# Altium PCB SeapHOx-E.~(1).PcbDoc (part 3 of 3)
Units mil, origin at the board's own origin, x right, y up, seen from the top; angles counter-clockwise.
Board outline 7300 x 3625 mil, 4 copper layers (Top Layer, Internal Plane 1, Signal Layer 1, Bottom Layer), stack 30.634 mil thick; 244 components, 217 nets, 966 pads, 416 vias.
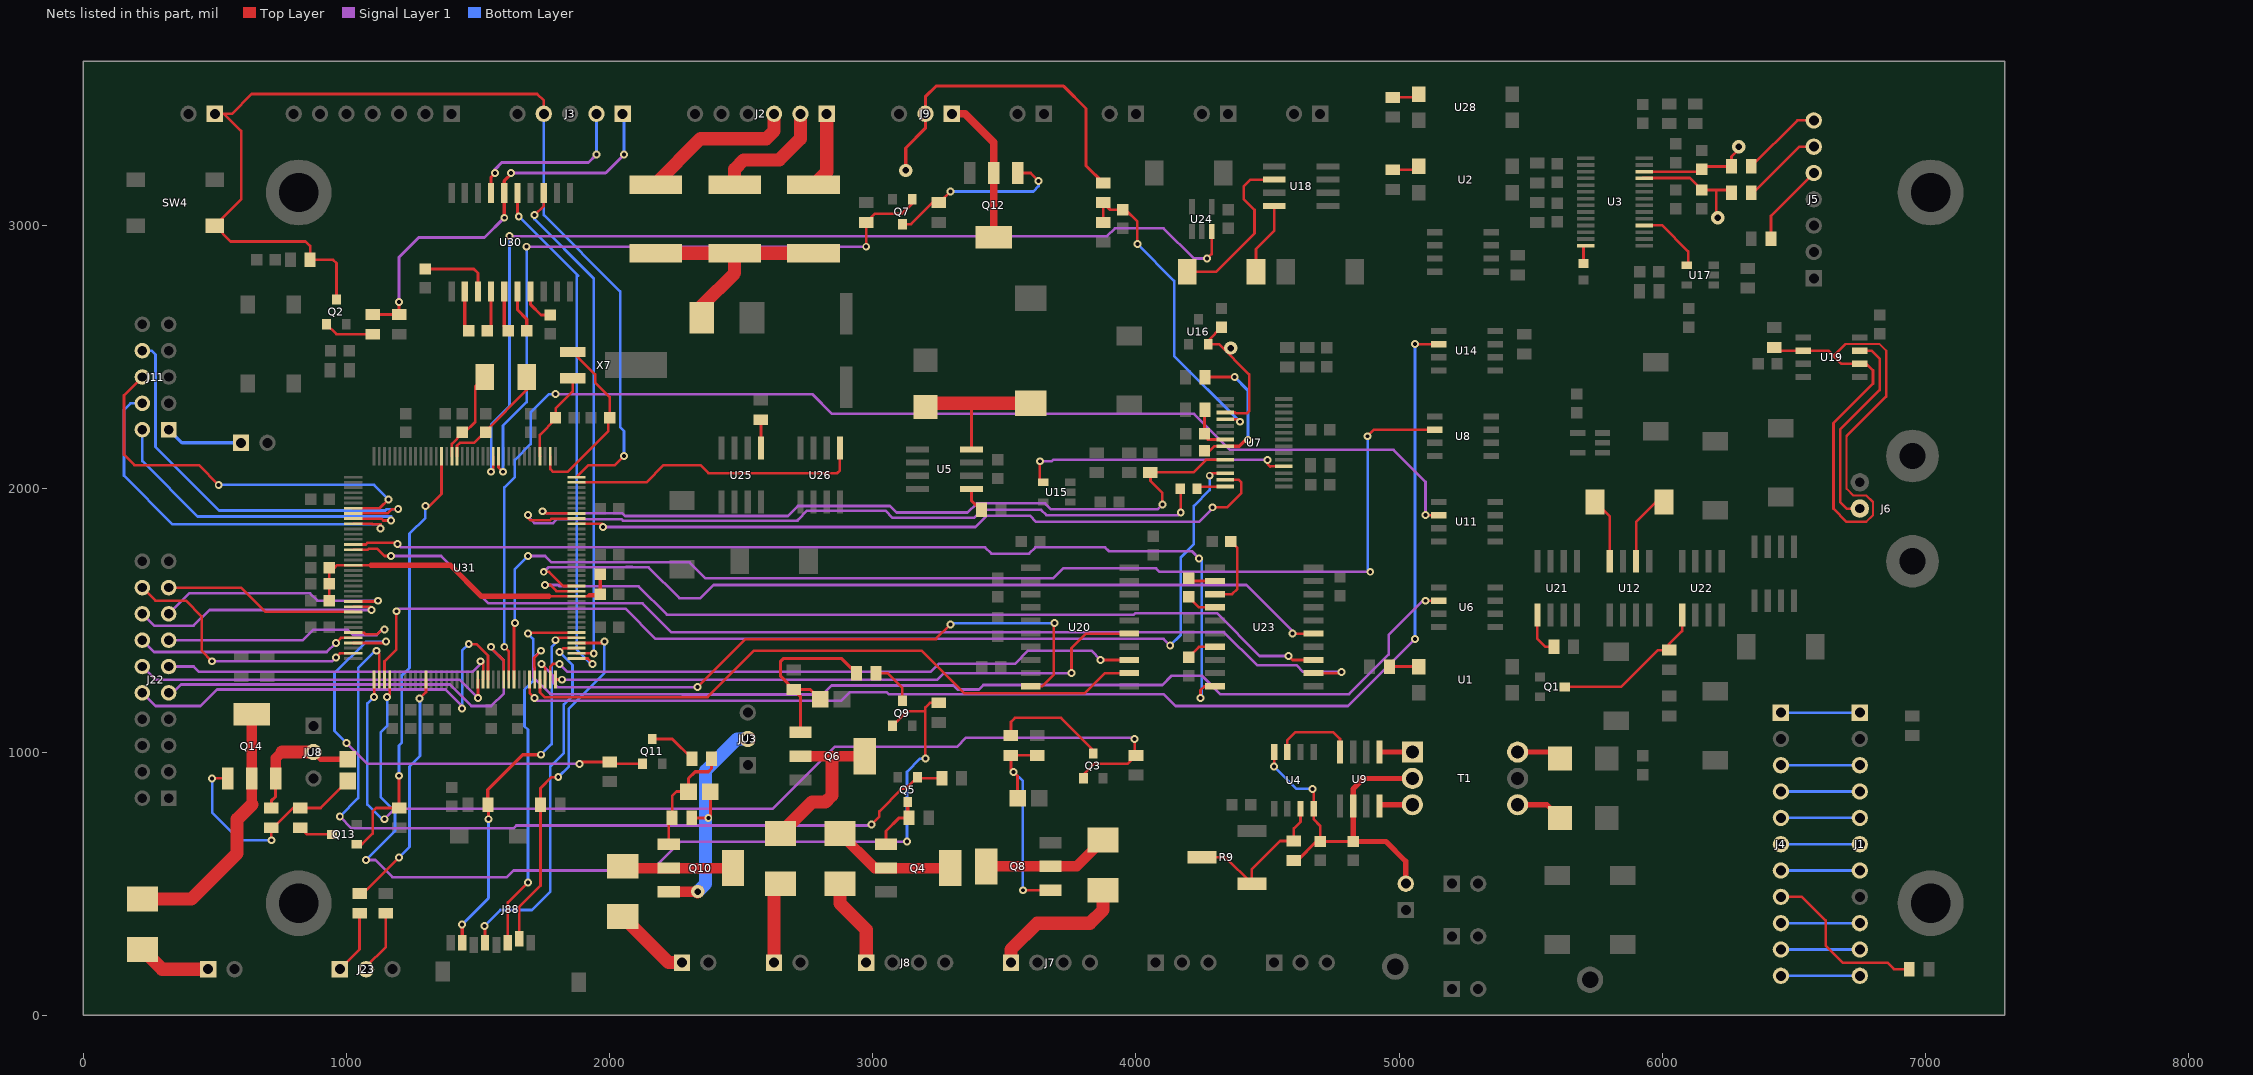
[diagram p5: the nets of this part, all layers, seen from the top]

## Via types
v1: diameter 30, hole 15, Top Layer to Bottom Layer, 378 vias
v2: diameter 50, hole 25, Top Layer to Bottom Layer, 38 vias

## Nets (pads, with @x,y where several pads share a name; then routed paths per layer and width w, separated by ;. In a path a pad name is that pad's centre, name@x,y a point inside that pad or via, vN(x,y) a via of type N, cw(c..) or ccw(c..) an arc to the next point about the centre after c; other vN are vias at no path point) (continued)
NetC41_1: C41.1 U12.2 | length 287
  Top Layer w10: U12.2@5900,1725 5900,1875 5975,1950 C41.1@6005.91,1950
NetC41_2: C41.2 U12.4 | length 248.2
  Top Layer w10: C41.2@5744.09,1950 5800,1894.09 U12.4@5800,1725
NetC42_1: C42.1 U23.2 | length 104.3
  Top Layer w10: C42.1@4200,1660.43 4210.43,1650 U23.2@4300,1650
NetC42_2: C42.2 U23.4 | length 116.4
  Top Layer w10: C42.2@4200,1589.57 4239.57,1550 U23.4@4300,1550
NetC43_1: C43.1 U23.7 | length 116.4
  Top Layer w10: C43.1@4200,1360.43 4239.57,1400 U23.7@4300,1400
NetC52_1: C52.1 U23.3 | length 283.5
  Top Layer w10: U23.3@4300,1600 4365,1600 4385,1620 4385,1775.43 C52.1@4360.43,1800
NetC53_2: C53.2 R33.1 U7.21 | length 184.4
  Top Layer w10: R33.1@4262.4,2300 4260.43,2298.03 C53.2@4260.43,2210 4260.43,2200 4272.64,2187.79 U7.21@4339,2187.79
NetC54_1: C54.1 C55.1 C56.1 C120.1 C121.1 U31.49 U31.126 | length 2218
  Top Layer w10: C54.1@935.43,1575 935.43,1625 C55.1@935.43,1640 ; C55.1@935.43,1658.43 C55.1@935.43,1640 ; 987,1710 1395,1710 1395.16,1709.84 1513.27,1591.73 1770,1591.73 U31.49@1874.24,1591.73 ; 1094.84,1709.84 U31.126@1025.76,1709.84 964.84,1709.84 955,1700 C120.1@935.43,1700 C55.1@935.43,1640 ; C121.1@1956.3,1591.73 U31.49@1874.24,1591.73 ; C121.1@1964.57,1600 1923.27,1600 1915,1591.73 U31.49@1874.24,1591.73
  Top Layer w12: C121.1@1964.57,1600 C56.1@1964.57,1675
  Top Layer w20: 1094.84,1709.84 1395.16,1709.84 1513.27,1591.73 1770,1591.73
NetC60_2: C60.2 R34.1 U7.22 | length 554.4
  Top Layer w10: C60.2@4260.43,2145 4280.43,2145 4297.64,2162.2 U7.22@4339,2162.2
  Top Layer w12: R34.1@4262.4,2425 v1(4375,2425) ; U7.22@4339,2162.2 4392.2,2162.2 4415,2185 v1(4425,2185)
  Bottom Layer w12: v1(4375,2425) 4425,2375 v1(4425,2185)
NetC62_1: C62.1 U18.2 | length 637.9
  Top Layer w10: C62.1@4194.09,2825 4305,2825 4450,2970 4450,3060 4410,3100 4410,3150 4435,3175 U18.2@4525,3175
NetC62_2: C62.2 U18.4 | length 278.6
  Top Layer w10: C62.2@4455.91,2825 4455.91,2910.91 4525,2980 U18.4@4525,3075
NetC101_1: C101.1 U30.7 | length 141.4
  Top Layer w12: U30.7@1700,2750 1700,2700 1739.57,2660.43 C101.1@1775,2660.43
NetC103_1: C103.1 U30.2 | length 156
  Top Layer w12: U30.2@1450,2750 1450,2614.57 C103.1@1464.57,2600
NetC103_2: C103.2 U30.4 | length 156
  Top Layer w12: C103.2@1535.43,2600 1550,2614.57 U30.4@1550,2750
NetC104_1: C104.1 U30.5 | length 156
  Top Layer w12: U30.5@1600,2750 1600,2614.57 C104.1@1614.57,2600
NetC104_2: C104.2 U30.6 | length 164.7
  Top Layer w12: U30.6@1650,2750 1650,2680 1685.43,2644.57 C104.2@1685.43,2600
NetC105_1: C105.1 U30.3 | length 276.4
  Top Layer w12: C105.1@1300,2835.43 1484.57,2835.43 1500,2820 U30.3@1500,2750
NetC122_1: C122.1 U31.74 X7.3 | length 698.1
  Top Layer w10: U31.74@1774.8,2124.24 1774.8,2075.2 1785,2065 1840,2065 1995,2220 1995,2264.57 C122.1@2000.43,2270 2000.43,2349.57 1945,2405 1945,2435 X7.3@1860,2520
NetC123_1: C123.1 U31.92 X6.2 | length 446.4
  Top Layer w10: U31.92@1420.47,2124.24 1420.47,2164.53 1430.94,2175 1485,2175 1522.5,2212.5 1522.5,2214.57 C123.1@1530,2214.57 1530,2220 1685,2375 X6.2@1685,2425
NetC124_1: C124.1 U31.93 X6.1 | length 357.8
  Top Layer w10: U31.93@1400.79,2124.24 1400.79,2170.79 1440,2210 C124.1@1440,2214.57 1449.57,2214.57 1490,2255 1490,2390 X6.1@1525,2425
NetC125_1: C125.1 U31.76 X7.1 | length 347.7
  Top Layer w10: U31.76@1735.43,2124.24 1735,2124.68 1735,2205 1795,2265 1795,2305 1860,2370 X7.1@1860,2420
NetD1_1: D1.1 T1.6 | length 171.8
  Top Layer w10: D1.1@5586.42,1000 D1.1@5611.42,975
  Top Layer w20: T1.6@5450,1000 D1.1@5586.42,1000
NetD2_1: D2.1 J2.1 | length 290.7
  Top Layer w50: D2.1@2775,3155 2825,3205 J2.1@2825,3425
NetD2_2: D2.2 D3.2 D7.2 FS1.1 | length 896.8
  Top Layer w50: D7.2@2175,2895 D3.2@2475,2895 ; FS1.1@2350,2650 2350,2695 2475,2820 D3.2@2475,2895 ; D2.2@2775,2895 D3.2@2475,2895
NetD3_1: D3.1 J2.2 | length 452.6
  Top Layer w50: D3.1@2475,3155 2475,3215 2510,3250 2645,3250 2725,3330 J2.2@2725,3425
NetD4_1: D4.1 T1.4 | length 182.1
  Top Layer w20: T1.4@5450,800 5561.42,800 D4.1@5611.42,750
NetD7_1: D7.1 J2.3 | length 602.8
  Top Layer w50: D7.1@2175,3155 2175,3160 2345,3330 2595,3330 2625,3360 J2.3@2625,3425
NetD8_2: D8.2 L1.1 U5.4 | length 602.7
  Top Layer w10: D8.2@3200,2311.42 3206.42,2305 3206.42,2325 D8.2@3213.58,2325 ; U5.4@3375,2150 3375,2325 3375,2330
  Top Layer w50: D8.2@3213.58,2325 3375,2325 L1.1@3600,2325
NetD9_1: D9.1 Q6.1 R29.1 R37.2 | length 731.2
  Top Layer w12: Q6.1@2725,1075 2725,1212.6 R29.1@2700,1237.6 ; D9.1@2800,1200 2762.4,1237.6 R29.1@2700,1237.6 ; R37.2@2937.6,1300 2882.6,1355 2660,1355 2650,1345 2650,1287.6 R29.1@2700,1237.6
NetD10_1: D10.1 Q8.1 R19.1 R38.2 | length 842.5
  Top Layer w10: D10.1@3550,825 3550,910 v1(3535,925) 3525,935 R38.2@3525,987.6 R19.1@3625,987.6 ; v1(3570,475) Q8.1@3675,475
  Bottom Layer w10: v1(3535,925) 3570,890 v1(3570,475)
NetD11_1: D11.1 Q10.1 R31.1 R39.2 | length 447.9
  Top Layer w10: Q10.1@2225,650 2225,737.4 R31.1@2237.6,750 2237.6,832.6 2255,850 D11.1@2300,850
  Top Layer w12: D11.1@2300,850 2300,900 2325,925 2375,925 2387.4,937.4 R39.2@2387.4,975
NetD11_2: D11.2 JU3.2 Q10.3 R31.2 | length 958.5
  Top Layer w12: R31.2@2312.4,750 v1(2375,750) 2383,758 D11.2@2383,850
  Top Layer w40: Q10.3@2225,468.9 v2@2333.9,468.9
  Top Layer w50: v2@2333.9,468.9 v2(2335,470)
  Bottom Layer w50: v2(2335,470) 2365,500 2365,750 2365,930 2485,1050 JU3.2@2525,1050
NetD12_1: D12.1 Q14.1 R42.1 R50.2 | length 869.6
  Top Layer w10: v1(490,900) Q14.1@550,900 ; v1(715,665) R42.1@715,712.6 722.6,712.6 797.4,787.4 R50.2@825,787.4 902.4,787.4 D12.1@1005,890
  Bottom Layer w10: v1(490,900) 490,770 595,665 v1(715,665)
NetD12_2: D12.2 JU8.2 Q14.3 R42.2 | length 490.4
  Top Layer w12: R42.2@715,787.4 715,815 731.1,831.1 Q14.3@731.1,900
  Top Layer w20: JU8.2@875,1000 902,973 D12.2@1005,973
  Top Layer w40: Q14.3@731.1,900 731.1,976.1 755,1000
  Top Layer w50: 755,1000 JU8.2@875,1000
NetFS2_1: FS2.1 J8.1 | length 341.4
  Top Layer w50: FS2.1@2875,500 2875,425 2975,325 J8.1@2975,200
NetFS2_2: FS2.2 Q4.2 Q4.4 | length 473.7
  Top Layer w40: FS2.2@2875,691.34 3006.89,559.45 Q4.2@3050,559.45 Q4.4@3294.1,559.45
NetFS3_1: FS3.1 J7.1 | length 537.1
  Top Layer w50: J7.1@3525,200 3525,250 3625,350 3825,350 3875,400 FS3.1@3875,475
NetFS3_2: FS3.2 Q8.2 Q8.4 | length 485.8
  Top Layer w40: Q8.4@3430.91,565.55 Q8.2@3675,565.55 3774.21,565.55 FS3.2@3875,666.34
NetFS4_1: FS4.1 J10.1 | length 310.4
  Top Layer w50: J10.1@2625,200 2625,475 FS4.1@2650,500
NetFS4_2: FS4.2 Q6.2 Q6.4 | length 762.5
  Top Layer w10: Q6.2@2725,984.45 2795,984.45 2804.45,975 2845,975
  Top Layer w40: Q6.2@2725,984.45 Q6.4@2969.09,984.45
  Top Layer w50: FS4.2@2650,691.34 2768.66,810 2820,810 2845,835 2845,975
NetFS5_1: FS5.1 J12.1 | length 297.5
  Top Layer w50: FS5.1@2050,375 2225,200 J12.1@2275,200
NetFS5_2: FS5.2 Q10.2 Q10.4 | length 435.7
  Top Layer w10: FS5.2@2050,566.34 2056.89,566.34 FS5.2@2056.89,559.45
  Top Layer w40: FS5.2@2056.89,559.45 Q10.2@2225,559.45 Q10.4@2469.09,559.45
  Top Layer w50: Q10.4@2462.2,566.34 Q10.4@2469.09,559.45
NetFS6_1: FS6.1 J20.1 | length 281.1
  Top Layer w50: FS6.1@225,250 300,175 J20.1@475,175
NetFS6_2: FS6.2 Q14.2 Q14.4 | length 984
  Top Layer w40: 640.55,800.55 Q14.2@640.55,900 Q14.4@640.55,1144.09
  Top Layer w50: FS6.2@225,441.34 411.34,441.34 585,615 585,745 640.55,800.55
NetJ1_1: J1.1 J4.1 | length 300
  Bottom Layer w10: J4.1@6450,1150 J1.1@6750,1150
NetJ1_3: J1.3 J4.3 | length 300
  Bottom Layer w10: J4.3@6450,950 J1.3@6750,950
NetJ1_4: J1.4 J4.4 | length 300
  Bottom Layer w10: J4.4@6450,850 J1.4@6750,850
NetJ1_5: J1.5 J4.5 | length 300
  Bottom Layer w10: J4.5@6450,750 J1.5@6750,750
NetJ1_6: J1.6 J4.6 | length 300
  Bottom Layer w10: J4.6@6450,650 J1.6@6750,650
NetJ1_7: J1.7 J4.7 | length 300
  Bottom Layer w10: J4.7@6450,550 J1.7@6750,550
NetJ1_9: J1.9 J4.9 | length 300
  Bottom Layer w10: J4.9@6450,350 J1.9@6750,350
NetJ1_10: J1.10 J4.10 | length 300
  Bottom Layer w10: J4.10@6450,250 J1.10@6750,250
NetJ1_11: J1.11 J4.11 | length 300
  Bottom Layer w10: J4.11@6450,150 J1.11@6750,150
NetJ3_2: J3.2 U30.17 | length 660
  Top Layer w12: U30.17@1550,3124.02 1550,3185 v1(1565,3200)
  Signal Layer 1 w12: v1(1565,3200) 1565,3215 1590,3240 1920,3240 v1(1950,3270)
  Bottom Layer w12: v1(1950,3270) J3.2@1950,3425
NetJ4_8: J4.8 R15.1 | length 657.2
  Top Layer w10: J4.8@6450,450 6530,450 6620,360 6620,265 6685,200 6855,200 6880,175 R15.1@6937.6,175
NetJ5_5: J5.5 R43.2 | length 317.4
  Top Layer w10: R43.2@6412.4,2950 6412.4,3037.4 J5.5@6575,3200
NetJ5_6: J5.6 R23.2 | length 310.1
  Top Layer w10: R23.2@6337.4,3125 6345,3125 6520,3300 J5.6@6575,3300
NetJ5_7: J5.7 R24.2 | length 310.1
  Top Layer w10: R24.2@6337.4,3225 6512.4,3400 J5.7@6575,3400
NetJ6_1: J6.1 U19.3 | length 779.9
  Top Layer w10: J6.1@6750,1925 6700,1925 6675,1950 6675,2225 6825,2375 6825,2495 6795,2525 U19.3@6750,2525
NetJ9_1: J9.1 Q12.2 Q12.4 | length 564.4
  Top Layer w30: J9.1@3300,3425 3350,3425 3459.45,3315.55 Q12.2@3459.45,3200 Q12.4@3459.45,2955.91
NetJ9_2: J9.2 R36.1 | length 1282.4
  Top Layer w12: v2(3125,3210) 3125,3295 3200,3370 J9.2@3200,3425 3200,3490 3240,3530 3725,3530 3810,3445 3810,3227.4 R36.1@3875,3162.4
NetJ11_1: J11.1 JU7.1 | length 295.7
  Bottom Layer w12: J11.1@325,2225 375,2175 JU7.1@600,2175
NetJ23_1: J23.1 R60.1 | length 243.7
  Top Layer w10: J23.1@975,175 1050,250 R60.1@1050,387.6
NetJ23_2: J23.2 R61.1 | length 243.7
  Top Layer w10: J23.2@1075,175 1075,185 1150,260 R61.1@1150,387.6
NetQ1_3: Q1.3 R5.2 U22.5 | length 607
  Top Layer w10: Q1.3@5629.49,1247.6 5842.6,1247.6 5982.4,1387.4 R5.2@6025,1387.4 6025,1410 6075,1460 U22.5@6075,1520.28
NetQ2_1: Q2.1 R55.1 | length 190.5
  Top Layer w10: Q2.1@925,2625 962.4,2587.6 R55.1@1100,2587.6
NetQ3_3: Q3.3 R38.1 | length 435
  Top Layer w10: R38.1@3525,1062.4 3525,1115 3540,1130 3715,1130 3837.4,1007.6 Q3.3@3837.4,994.49
NetQ4_1: Q4.1 Q5.3 R22.1 | length 206.2
  Top Layer w12: Q4.1@3050,650 3050,700 3100,750 R22.1@3132.6,750 ; R22.1@3132.6,757.6 Q5.3@3132.6,810.51
NetQ7_3: Q7.3 Q12.1 R26.1 | length 689.7
  Top Layer w10: Q7.3@3112.6,3005.51 3145.51,3005.51 3227.4,3087.4 R26.1@3250,3087.4 3252.4,3087.4 v1(3295,3130) ; Q12.1@3550,3200 3600,3200 v1(3630,3170)
  Bottom Layer w10: v1(3295,3130) 3610,3130 3630,3150 v1(3630,3170)
NetQ9_3: Q9.3 R37.1 | length 171.9
  Top Layer w10: R37.1@3012.4,1300 3055,1300 3112.4,1242.6 Q9.3@3112.4,1194.49
NetQ11_3: Q11.3 R39.1 | length 181
  Top Layer w10: Q11.3@2162.4,1049.49 2238.11,1049.49 R39.1@2312.6,975
NetQ13_3: Q13.3 R50.1 | length 130.9
  Top Layer w10: R50.1@825,712.6 850.2,687.4 Q13.3@945.51,687.4
NetR1_2: R1.2 U1.1 | length 112.6
  Top Layer w10: R1.2@4962.4,1325 U1.1@5075,1325
NetR7_1: R7.1 R9.1 R9.2 U4.7 | length 623.9
  Top Layer w10: R9.2@4250,600 4340,600 R9.1@4440,500 4440,555 4547.4,662.4 R7.1@4600,662.4 4600,710 4625,735 U4.7@4625,785
NetR8_2: R8.2 U5.1 | length 97.1
  Top Layer w12: U5.1@3375,2000 3375,1955 3410,1920 R8.2@3412.6,1920
NetR10_1: R10.1 U21.5 | length 165.3
  Top Layer w10: U21.5@5525,1520.28 5525,1430 5555,1400 R10.1@5587.6,1400
NetR11_1: R11.1 U25.5 | length 107.9
  Top Layer w12: U25.5@2575,2154.72 R11.1@2575,2262.6
NetR17_2: R17.2 U3.28 | length 71.2
  Top Layer w10: R17.2@5700,2856.5 5700,2918.5 U3.28@5706.5,2925
NetR21_1: R21.1 U19.2 U19.6 | length 2173.7
  Top Layer w8: 6695,2550 6825,2550 6850,2525 ; 6700,1875 6775,1875 6800,1900 6800,1950 6775,1975 6725,1975 6700,2000 6700,2200
  Top Layer w10: R21.1@6425,2537.6 6437,2537.6 6437,2525 U19.6@6535,2525 6630,2525 6650,2505 ; 6695,2550 6650,2505 ; 6700,1875 6650,1925 6650,2250 6800,2400 6800,2450 6775,2475 U19.2@6750,2475 6680,2475 6650,2505 ; 6700,2200 6850,2350 6850,2525
NetR53_2: R53.2 U7.28 | length 116.2
  Top Layer w10: R53.2@4231.5,2000 4231.5,2008.66 4240.16,2008.66 U7.28@4339,2008.66
NetR56_2: R56.2 U2.1 | length 92
  Top Layer w10: R56.2@4975,3212.4 5062.4,3212.4 U2.1@5067,3212.4
NetR59_2: R59.2 U28.1 | length 92
  Top Layer w10: R59.2@4975,3487.4 5062.4,3487.4 U28.1@5067,3487.4
NetT1_1: T1.1 U9.1 | length 125
  Top Layer w20: U9.1@4925,1000 T1.1@5050,1000
NetT1_3: T1.3 U9.8 | length 129.7
  Top Layer w10: U9.8@4925,795.28 4925,800 U9.8@4929.72,800
  Top Layer w20: U9.8@4929.72,800 T1.3@5050,800
NetU3_4: U3.4 U17.4 | length 266.4
  Top Layer w10: U3.4@5925,3001.77 5998.23,3001.77 6097.64,2902.36 U17.4@6097.64,2849.8
NetU4_3: U4.3 U9.4 | length 317.8
  Top Layer w10: U4.3@4575,1000 4575,1045 4605,1075 4750,1075 4775,1050 U9.4@4775,1000
NetU7_4: U7.4 U15.4 | length 1033.1
  Top Layer w10: v1(3635,2105) 3635,2037.44 U15.4@3647.64,2024.8 ; v1(4500,2110) 4500,2095 4510,2085 4510,2085.43 U7.4@4561,2085.43
  Signal Layer 1 w10: v1(3635,2105) 3680,2105 3685,2110 v1(4500,2110)
PB5: J22.17 U31.135 | length 739
  Top Layer w10: J22.17@325,1625 600,1625 692.32,1532.68 U31.135@1025.76,1532.68
PD6: J22.18 U31.143 | length 1005.4
  Top Layer w10: J22.18@225,1625 275,1575 390,1575 450,1515 450,1385 v1(490,1345) ; v1(960,1360) 975.2,1375.2 U31.143@1025.76,1375.2
  Signal Layer 1 w10: v1(490,1345) 945,1345 v1(960,1360)
PE4: J22.13 U31.139 | length 982.7
  Top Layer w10: U31.139@1025.76,1453.94 1066.47,1453.94 1073.4,1447 1117,1447 1135,1465 v1(1145,1465)
  Signal Layer 1 w10: J22.13@325,1425 835,1425 875,1465 1005,1465 1025,1445 1115,1445 1135,1465 v1(1145,1465)
PE5: J22.14 U31.140 | length 841.9
  Top Layer w10: v1(960,1415) 979.25,1434.25 U31.140@1025.76,1434.25
  Signal Layer 1 w10: J22.14@225,1425 270,1380 925,1380 v1(960,1415)
PE6: J22.15 U31.133 | length 935.2
  Top Layer w10: U31.133@1025.76,1572.05 v1@1115,1572.05 ; v1@1115,1570 v1(1120,1575)
  Signal Layer 1 w10: J22.15@325,1525 403,1603 862,1603 890,1575 v1(1120,1575)
PE7: J22.16 U31.134 | length 997.9
  Top Layer w10: U31.134@1025.76,1552.36 1092.64,1552.36 1095,1550 v1(1095,1540)
  Signal Layer 1 w10: J22.16@225,1525 270,1480 420,1480 480,1540 1085,1540 1090,1545 v1@1095,1550
"PH +5V": C25.1 C36.2 JU2.2 R7.2 T1.2 U4.4 U4.8 U9.6 | length 1459.8
  Top Layer w10: v1(4525,945) U4.4@4525,1000 ; R7.2@4600,587.6 R7.2@4612.6,587.6 ; v1(4670,860) 4675,855 U4.8@4675,785 4675,745 4700,720 C36.2@4700,660.43 C36.2@4685.43,660.43
  Top Layer w12: R7.2@4612.6,587.6 C36.2@4685.43,660.43 ; C36.2@4700,660.43 C25.1@4825,660.43
  Top Layer w20: JU2.2@5025,500 5025,585 4949.57,660.43 C25.1@4825,660.43 U9.6@4825,795.28 4825,860 4865,900 T1.2@5050,900
  Bottom Layer w10: v1(4525,945) 4610,860 v1(4670,860)
PRES_V_DIV: C15.2 R35.1 R36.2 U7.18 | length 1219.7
  Top Layer w10: R35.1@3875,3012.4 R36.2@3875,3087.6 3902.16,3060.43 C15.2@3950,3060.43 3959.57,3060.43 4005,3015 v1(4005,2930) ; U7.18@4339,2264.57 4390.43,2264.57 4395,2260 v1(4395,2255)
  Bottom Layer w10: v1(4005,2930) 4145,2790 4145,2505 v1(4395,2255)
RED-LED: R60.2 U31.11 | length 929.8
  Top Layer w10: R60.2@1050,462.4 1062.4,462.4 v1(1200,600) ; v1(1277.5,1203.77) 1277.5,1202.5 1278.13,1203.13 1302.36,1227.36 U31.11@1302.36,1275.76
  Bottom Layer w10: v1(1200,600) 1240,640 1240,945 1280,985 1280,1201.27 v1(1277.5,1203.77)
RSRXD: J3.1 R54.2 R55.2 U30.16 | length 1588.2
  Top Layer w12: R55.2@1100,2662.4 R54.2@1200,2662.4 v1(1200,2710) ; v1(1600,3030) U30.16@1600,3124.02 1600,3170 v1@1630,3200
  Signal Layer 1 w12: v1(1200,2710) 1200,2880 1275,2955 1525,2955 v1(1600,3030) ; v1(1625,3200) 1985,3200 v1(2055,3270)
  Bottom Layer w12: J3.1@2050,3425 2055,3430 v1(2055,3270)
SSI0CLK: J88.5 U31.39 | length 1405.1
  Top Layer w10: v1(1810,1380) 1824.88,1394.88 U31.39@1874.24,1394.88
  Top Layer w12: v1(1525,340) 1526.77,338.23 J88.5@1526.77,275
  Bottom Layer w10: v1(1525,340) 1585,400 1705,400 1775,470 1775,945 1826,996 1826,1181 1859,1214 1859,1331 v1(1810,1380)
SSI0FSS: J88.2 R45.1 U31.40 | length 1385.8
  Top Layer w10: J88.2@1656.69,290.75 1656.69,411.69 1737.6,492.6 R45.1@1737.6,800 1737.6,862.6 1780,905 v1(1805,905) ; U31.40@1874.24,1414.57 1974.57,1414.57 v1(1980,1420)
  Bottom Layer w10: v1(1805,905) 1845,945 1845,1165 1980,1300 v1(1980,1420)
SSI0RX: J88.7 R51.1 U31.41 | length 1423.3
  Top Layer w10: v1(1795,1425) 1804.25,1434.25 U31.41@1874.24,1434.25
  Top Layer w12: v1(1440,345) 1440.16,344.84 J88.7@1440.16,275 ; v1(1540,745) 1540,797.4 R51.1@1537.4,800 1537.4,857.4 1670,990 v1(1740,990)
  Bottom Layer w10: v1(1740,990) 1780,1030 1780,1400 1795,1415 v1(1795,1425)
  Bottom Layer w12: v1(1440,345) 1540,445 v1(1540,745)
SSI0TX: J88.3 U31.42 | length 1419.9
  Top Layer w10: J88.3@1613.39,275 1613.39,428.39 v1(1690,505) ; v1(1690,1450) 1693.94,1453.94 U31.42@1874.24,1453.94
  Bottom Layer w10: v1(1690,505) 1690,1085 1677,1098 1677,1237 1710,1270 1710,1430 v1(1690,1450)
SSI1CLK: R53.1 U31.64 | length 2875.5
  Top Layer w10: v1(1690,1900) 1700,1900 1690,1890 1699.69,1880.31 1773.29,1880.31 1779.99,1887.01 U31.64@1874.24,1887.01 ; R53.1@4168.5,2000 4170,1998.5 v1(4170,1910)
  Signal Layer 1 w10: v1(1690,1900) 1700,1900 1692.5,1892.5 1715,1870 1785,1870 1800,1885 2044.95,1885 2050.95,1879 2715,1879 2715,1882 2750,1917 3048,1917 3075,1890 3385,1890 3415,1920 3640,1920 3660,1900 4160,1900 v1(4170,1910)
SSI1FSS: R47.1 U7.24 U31.65 | length 3017.5
  Top Layer w10: v1(1745,1915) v1@1755,1915 ; v1@1753.31,1906.69 U31.65@1874.24,1906.69 ; R47.1@4070,2047.6 R47.1@4055,2062.6 ; v1(4100,1940) 4100,1985 4055,2030 R47.1@4055,2062.6 ; U7.24@4339,2111.02 4338.32,2110.35 4265.35,2110.35 4217.6,2062.6 R47.1@4055,2062.6
  Signal Layer 1 w10: v1(1745,1915) 1755,1915 1763,1907 2048.4,1907 2058.4,1897 2677,1897 2715,1935 3065,1935 3090,1910 3360,1910 3395,1945 3655,1945 3678,1922 4082,1922 v1(4100,1940)
SSI1RX: U7.26 U31.3 | length 4053.8
  Top Layer w10: U31.3@1144.88,1275.76 1144.88,1344.88 1190,1390 v1(1190,1535) ; v1(4280,2050) 4289.84,2059.84 U7.26@4339,2059.84
  Signal Layer 1 w10: v1(1190,1535) 1200,1545 2060,1545 2175,1430 4105,1430 v1(4130,1405)
  Bottom Layer w10: v1@4127.5,1402.5 v1(4130,1405) 4170,1445 4170,1740 4220,1790 4220,1935 4280,1995 v1(4280,2050)
SSI1TX: U7.27 U31.63 | length 2715.9
  Top Layer w10: U31.63@1874.24,1867.32 1972.68,1867.32 1975,1865 v1(1975,1855) ; v1(4290,1930) 4345,1930 4400,1985 4400,2025 4390.75,2034.25 U7.27@4339,2034.25
  Signal Layer 1 w10: v1(1975,1855) 3390,1855 3433,1898 3598,1898 3621,1875 4240,1875 v1@4292.5,1927.5
SSI2CLK: J22.9 U31.26 | length 1681.3
  Top Layer w10: v1(1550,1400) 1555,1395 1555,1390 1598,1347 1598,1276.12 U31.26@1597.64,1275.76
  Signal Layer 1 w10: J22.9@325,1225 340,1225 372,1257 1393,1257 1475,1175 1550,1175 1598,1223 1598,1347 1550,1395 v1(1550,1400)
SSI2FSS: J22.10 U31.23 | length 1735.6
  Top Layer w10: v1(1465,1410) 1495,1410 1538,1367 1538,1276.34 U31.23@1538.58,1275.76
  Signal Layer 1 w10: J22.10@225,1225 275,1175 446,1175 509,1238 1377,1238 1440,1175 v1(1440,1165)
  Bottom Layer w10: v1(1440,1165) 1440,1385 v1(1465,1410)
SSI2RX: J22.11 U31.22 | length 1295.4
  Top Layer w10: v1(1510,1345) 1520,1345 1520,1276.86 U31.22@1518.9,1275.76
  Signal Layer 1 w10: J22.11@325,1325 420,1325 440,1305 1480,1305 1510,1335 v1(1510,1345)
SSI2TX: J22.12 U31.21 | length 1395.8
  Top Layer w10: U31.21@1499.21,1275.76 1500,1274.97 v1(1500,1205)
  Signal Layer 1 w10: J22.12@225,1325 275,1275 1430,1275 v1(1500,1205)
SSI3CLK: U6.2 U31.32 | length 3962.3
  Top Layer w10: U31.32@1715.75,1275.76 1715.75,1320.65 1714,1322.4 1714,1359 v1(1740,1385) ; v1(5100,1575) U6.2@5150,1575
  Signal Layer 1 w10: v1(1740,1385) 1710,1355 1710,1285 1775,1220 2275,1220 2276,1219 2809,1219 2843,1253 3307,1253 3322,1238 3403,1238 3420,1255 4100,1255 4135,1290 4250,1290 4320,1220 4810,1220 4960,1370 4960,1445 5090,1575 v1(5100,1575)
SSI3FSS: U14.2 U31.31 | length 4779
  Top Layer w10: U31.31@1696.06,1275.76 1696.06,1223.94 v1(1715,1205) ; v1(5060,2550) U14.2@5150,2550
  Signal Layer 1 w10: v1(1715,1205) 1725,1195 2880,1195 2913,1228 3052,1228 3060,1220 4105,1220 4150,1175 4805,1175 v1(5060,1430)
  Bottom Layer w10: v1(5060,1430) v1(5060,2550)
SSI3RX: U8.6 U31.28 | length 4532
  Top Layer w10: U31.28@1637.01,1275.76 1637.01,1487.01 v1(1640,1490) ; v1(4880,2200) 4905,2225 U8.6@5135,2225
  Signal Layer 1 w10: v1(1690,1745) 1705,1745 1755,1745 1779,1721 2304,1721 2365,1660 3685,1660 3723,1698 4076.6,1698 4089.6,1685 v1(4890,1685)
  Bottom Layer w10: v1(1640,1490) 1640,1695 v1(1690,1745) ; v1(4880,2200) 4880,1695 v1(4890,1685)
SSI3TX: U11.2 U31.27 | length 4806.8
  Top Layer w10: v1(1600,1400) 1617.32,1382.68 U31.27@1617.32,1275.76 ; v1(5100,1900) U11.2@5150,1900
  Signal Layer 1 w10: v1(1795,2360) 2770,2360 2845,2285 4221,2285 4358,2148 4979,2148 5100,2027 v1(5100,1900)
  Bottom Layer w10: v1(1600,1400) 1600,2005 1640,2045 1640,2110 1700,2170 1700,2290 1770,2360 v1(1795,2360)
SWITCH_2.5V: U24.3 U31.85 | length 3806.9
  Top Layer w10: v1(1550,2065) 1558.27,2073.27 U31.85@1558.27,2124.24 ; v1(4270,2875) 4287.4,2892.4 U24.3@4287.4,2978
  Signal Layer 1 w10: v1(1620,2960) 3890,2960 3920,2990 4105,2990 4220,2875 v1(4270,2875)
  Bottom Layer w10: v1(1550,2065) 1550,2245 1620,2315 v1(1620,2960)
SWITCH_AUX_POWER1: Q11.1 R32.2 U31.141 | length 1808.6
  Top Layer w10: U31.141@1025.76,1414.57 1144.57,1414.57 v1(1150,1420) ; v1(1885,955) 1892.4,962.4 R32.2@2000,962.4 ; R32.2@2007.4,955 Q11.1@2125,955
  Signal Layer 1 w10: v1(1000,1035) 1080,955 v1(1885,955)
  Bottom Layer w10: v1(1000,1035) 955,1080 955,1300 1074,1419 1149,1419 v1(1150,1420)
SWITCH_AUX_POWER2: Q13.1 R44.2 U31.95 | length 1679.2
  Top Layer w10: Q13.1@1040,650 1060,650 1100,690 1100,775 1112.4,787.4 R44.2@1200,787.4 v1(1200,910) ; v1(1300,1935) 1315,1935 1361.42,1981.42 U31.95@1361.42,2124.24
  Bottom Layer w10: v1(1200,910) 1200,1025 1210,1035 1210,1290 1240,1320 1240,1829.54 1300,1889.54 v1(1300,1935)
SWITCH_MCAT: Q3.1 R20.2 U31.1 | length 3867.2
  Top Layer w10: v1(1105,1210) 1105.51,1210.51 U31.1@1105.51,1275.76 ; Q3.1@3800,900 3800,915 3840,955 3967.6,955 R20.2@4000,987.4 R20.2@3995,992.4 ; R20.2@3992.91,994.49 R20.2@3995,992.4 ; v1(3995,1050) R20.2@3995,992.4
  Signal Layer 1 w10: v1(1145,745) 1185,785 2620,785 2855,1020 3320,1020 3355,1055 3990,1055 v1(3995,1050)
  Bottom Layer w10: v1(1105,1210) 1080,1185 1080,800 1135,745 v1(1145,745)
SWITCH_OPTODE: Q5.1 R25.2 U31.2 | length 3205.2
  Top Layer w10: v1(1115,1385) 1125.2,1374.8 U31.2@1125.2,1275.76 ; v1(2995,725) 3025,755 3025,775 3110,860 3125,860 Q5.1@3170,905 ; Q5.1@3175,900 R25.2@3262.6,900
  Signal Layer 1 w10: v1(975,755) 1020,710 1635,710 1646,721 v1@2991,721
  Signal Layer 1 w12: v1@2991,721 v1(2995,725)
  Bottom Layer w10: v1(975,755) 1045,825 1045,1320 v1@1115,1390
  Bottom Layer w12: v1(1115,1385) v1@1115,1390
SWITCH_OPTOISO: U26.5 U31.71 | length 1129.1
  Top Layer w10: U31.71@1874.24,2024.8 2139.8,2024.8 2205,2090 2345,2090 2375,2060 2865,2060 2875,2070 U26.5@2875,2154.72
SWITCH_PRESSURE: Q7.1 R28.2 U31.84 | length 2561.2
  Top Layer w10: U31.84@1577.95,2124.24 1577.95,2082.05 v1(1595,2065) ; v1(2975,2920) R28.2@2975,3012.6 3007.4,3045 3110,3045 3150,3085 Q7.1@3150,3100
  Signal Layer 1 w10: v1(1685,2920) v1(2975,2920)
  Bottom Layer w10: v1(1595,2065) 1595,2240 1685,2330 v1(1685,2920)
SWITCH_PUMP: Q9.1 R30.2 U31.4 | length 3657
  Top Layer w10: v1(1155,1210) 1164.57,1219.57 U31.4@1164.57,1275.76 ; Q9.1@3075,1100 3130,1155 3195,1155 ; v1(3200,975) 3200,1170 3217.4,1187.4 R30.2@3250,1187.4
  Signal Layer 1 w10: v1(1075,590) 1110,590 1175,525 1610,525 1635,550 2160,550 2270,660 v1(3130,660)
  Bottom Layer w10: v1(1075,590) 1185,700 1185,775 1130,830 1130,1075 1155,1100 v1(1155,1210) ; v1(3130,660) 3130,925 3180,975 v1(3200,975)
TCK: J11.4 U31.118 | length 1487.2
  Top Layer w10: U31.118@1025.76,1867.32 1097.68,1867.32 1100,1865 1130,1865
  Bottom Layer w10: J11.4@225,2325 180,2325 155,2300 155,2050 340,1865 1130,1865
  other v1: 1130,1850
TDI: J11.8 U31.116 | length 1608.5
  Top Layer w10: U31.116@1025.76,1906.69 1157.09,1906.69 1173.4,1923 v1(1197,1923)
  Bottom Layer w10: J11.8@225,2525 260,2525 275,2510 275,2160 516.94,1918.06 1148.06,1918.06 1153,1923 v1(1197,1923)
TDO: J11.6 U31.115 | length 1547.6
  Top Layer w10: J11.6@225,2425 155,2355 155,2130 195,2090 440,2090 v1(515,2015) ; U31.115@1025.76,1926.38 1126.38,1926.38 v1(1160,1960)
  Bottom Layer w10: v1(515,2015) 1105,2015 v1(1160,1960)
TEMP_VOLT: C10.1 U7.17 U16.2 | length 523.8
  Top Layer w10: C10.1@4325,2614.57 4274.8,2564.37 U16.2@4274.8,2550 4315,2550 4430,2435 4430,2295 4422,2287 4378.4,2287 4375.4,2290 4339.16,2290 U7.17@4339,2290.16
  other v2: 4360,2535
TMS: J11.2 U31.117 | length 1314.1
  Top Layer w10: U31.117@1025.76,1887.01 1133.45,1887.01 1140.46,1880 v1(1170,1880)
  Bottom Layer w10: J11.2@225,2225 225,2105 435,1895 1170,1895 v1(1170,1880)
U0RX: U30.15 U31.37 | length 1985.4
  Top Layer w10: U30.15@1650,3124.02 1650,3040 v1(1655,3035) ; U31.37@1874.24,1355.51 1916.52,1355.51 1937.03,1335 v1(1935,1335)
  Bottom Layer w10: v1(1655,3035) 1880,2810 ; 1875,2810 1875,1390 1930,1335 v1(1935,1335)
U0TX: U30.13 U31.38 | length 1922
  Top Layer w10: v1(1715,3040) 1750,3075 U30.13@1750,3124.02 ; U31.38@1874.24,1375.2 v1(1939.8,1375.2)
  Bottom Layer w10: v1(1715,3040) 1715,3025 1939.8,2800.2 v1(1939.8,1375.2)
"U2RX (AUX1)": U23.15 U31.51 | length 3229.9
  Top Layer w10: v1(1750,1685) 1770,1685 1823.9,1631.1 U31.51@1874.24,1631.1 ; v1(4595,1450) U23.15@4674.02,1450
  Signal Layer 1 w10: v1(1750,1685) 1767,1702 2062.4,1702 2063.4,1703 2086.6,1703 2087.6,1702 2148,1702 2265,1585 2345,1585 2395,1635 4419.6,1635 4595,1459.6 v1(4595,1450)
"U2TX (AUX1)": U23.13 U31.50 | length 3171.1
  Top Layer w10: v1(1755,1635) 1775,1635 1798.58,1611.42 U31.50@1874.24,1611.42 ; v1(4580,1365) 4595,1350 U23.13@4674.02,1350
  Signal Layer 1 w10: v1(1755,1635) 1805,1635 1810,1630 2110,1630 2218,1522 3992,1522 3998,1528 4307,1528 4470,1365 v1(4580,1365)
"U3RX (OPTODE)": U20.10 U31.34 | length 2462
  Top Layer w10: v1(1742,1334) 1755.12,1320.88 U31.34@1755.12,1275.76 ; v1(2334,1247) 2515,1428 3241,1428 3241,1431 v1(3295,1485) ; U20.10@3600,1250 3643,1250 3688,1295 v1@3688,1485
  Signal Layer 1 w10: v1(1742,1334) 1787,1289 1787,1263 1803,1247 v1(2334,1247)
  Bottom Layer w10: v1(3295,1485) 3300,1490 v1(3690,1490)
"U3TX (OPTODE)": U20.12 U31.33 | length 2466.7
  Top Layer w10: U31.33@1735.43,1275.76 1735.43,1227 1753.43,1209 2372,1209 2548,1385 3186,1385 3348,1223 3805,1223 3882,1300 U20.12@3974.02,1300
"U4RX (MCAT)": U20.15 U31.36 | length 2310.8
  Top Layer w10: U31.36@1794.49,1275.76 1819.24,1275.76 v1(1820,1275) ; v1(3755,1300) 3755,1395 3810,1450 U20.15@3974.02,1450
  Signal Layer 1 w10: v1(1820,1275) 3245,1275 3270,1300 v1(3755,1300)
  Bottom Layer w10: v1@3753,1302 v1(3755,1300)
"U4TX (MCAT)": U20.13 U31.35 | length 2312.5
  Top Layer w10: U31.35@1774.8,1275.76 1774.8,1324.8 1785,1335 v1(1810,1335) ; v1(3865,1350) U20.13@3974.02,1350
  Signal Layer 1 w10: v1(1810,1335) 1840,1305 3220,1305 3250,1335 3540,1335 3590,1385 3830,1385 v1(3865,1350)
"U5RX (AUX2)": U23.10 U31.122 | length 3889.1
  Top Layer w10: U31.122@1025.76,1788.58 1073.58,1788.58 1080,1795 1190,1795 v1(1195,1790) ; v1(4245,1205) 4245,1235 4260,1250 U23.10@4300,1250
  Signal Layer 1 w10: v1(1195,1790) 1207,1778 3427,1778 3451,1754 3594,1754 3618,1778 3882,1778 3897,1763 4212,1763 v1(4240,1735)
  Bottom Layer w10: v1(4240,1735) 4250,1725 4250,1210 v1(4245,1205)
"U5TX (AUX2)": U23.12 U31.123 | length 4062.9
  Top Layer w10: U31.123@1025.76,1768.9 1081.9,1768.9 1086,1773 1117,1773 1145,1745 v1(1170,1745) ; U23.12@4674.02,1300 4775,1300 v1(4780,1305)
  Signal Layer 1 w10: v1(1170,1745) 1360,1745 1540,1565 2125,1565 2235,1455 4335,1455 4460,1330 4610,1330 4635,1305 v1(4780,1305)
  Bottom Layer w10: v1@4775,1305 v1(4780,1305)
VINT: C49.2 R24.1 U3.12 | length 432.9
  Top Layer w10: U3.12@5925,3206.5 5926.58,3204.91 6140.35,3204.91 C49.2@6150,3214.57 6160.43,3225 R24.1@6262.6,3225 6262.6,3262.6 6290,3290 v2(6290,3300)
VTHERM: C48.1 R23.1 U3.11 | length 468.3
  Top Layer w10: U3.11@5925,3180.91 6104.53,3180.91 C48.1@6150,3135.43 6205,3135.43 ; v2(6210,3030) 6205,3035 6205,3135.43 ; R23.1@6262.6,3125 6252.17,3135.43 6205,3135.43
WAKE: J3.4 J21.1 Q2.3 R57.2 SW4.4 U31.72 | length 4165.4
  Top Layer w10: J21.1@500,3425 535,3425 ; Q2.3@962.4,2719.49 962.4,2857.4 949.8,2870 R57.2@862.4,2870 862.4,2922.6 845,2940 560,2940 SW4.4@500,3000 600,3100 600,3360 535,3425 ; J3.4@1750,3425 1750,3475 1725,3500 640,3500 565,3425 535,3425 ; U31.72@1874.24,2044.49 1919.76,2090 2020,2090 v1(2055,2125)
  Bottom Layer w10: J3.4@1750,3425 1750,3040 2040,2750 2040,2235 2055,2220 v1(2055,2125)
pads on no net: J6.0 J11.7 J88.0 J88.1 J88.8 SW3.1 SW3.3 SW4.1 SW4.3 U3.5 U3.6 U3.19 U3.20 U4.5 U5.6 U5.7 U6.3 U6.7 U7.5 U7.6 U7.19 U7.20 U8.3 U8.7 U9.3 U9.5 U11.3 U11.7 U12.1 U12.7 U13.1 U13.7 U14.3 U14.7 U18.1 U18.7 U19.1 U19.5 U19.8 U20.11 U20.14 U21.4 U22.2 U22.4 U23.11 U23.14 U25.2 U25.4 U26.2 U26.4 U29.3 U29.7 U30.8 U30.9 U30.10 U30.11 U30.14 U31.16 U31.17 U31.20 U31.45 U31.46 U31.47 U31.48 U31.52 U31.53 U31.54 U31.55 U31.58 U31.61 U31.62 U31.73 U31.80 U31.81 U31.82 U31.83 U31.86 U31.87 U31.88 U31.89 U31.96 U31.97 U31.98 U31.103 U31.104 U31.105 U31.106 U31.107 U31.109 U31.110 U31.111 U31.120 U31.121 U31.127 U31.128 U31.129 U31.130 U31.136 U31.142 U31.144 X7.2

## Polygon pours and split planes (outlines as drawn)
ISO_GND on Internal Plane 1 (split plane): 7279.9,20.1 5261.05,20.1 5261.05,3604.9 7279.9,3604.9
GND on Internal Plane 1 (split plane): 5248.95,20.1 20.1,20.1 20.1,3604.9 2944.9,3604.9 2944.9,3325 2945.29,3323.05 2946.4,3321.4 2971.4,3296.4 2973.05,3295.29 2975,3294.9 3572.89,3294.9 3707.4,3160.39 3707.4,2962.5 3707.79,2960.55 3708.9,2958.9 3783.9,2883.9 3785.55,2882.79 3787.5,2882.4 3835.39,2882.4 4119.9,2597.89 4119.9,2200 4120.29,2198.05 4121.4,2196.4 4171.4,2146.4 4173.05,2145.29 4175,2144.9 4425,2144.9 4426.95,2145.29 4428.61,2146.4 4429.71,2148.05 4430.1,2150 4429.71,2151.95 4428.61,2153.61 4426.95,2154.71 4425,2155.1 4177.11,2155.1 4130.1,2202.11 4130.1,2600 4129.71,2601.95 4128.61,2603.61 3841.11,2891.11 3839.45,2892.21 3837.5,2892.6 3789.61,2892.6 3717.6,2964.61 3717.6,3162.5 3717.21,3164.45 3716.11,3166.11 3578.61,3303.61 3576.95,3304.71 3575,3305.1 2977.11,3305.1 2955.1,3327.11 2955.1,3604.9 4894.9,3604.9 4894.9,3550 4894.9,2277.11 4772.89,2155.1 4475,2155.1 4473.05,2154.71 4471.4,2153.61 4470.29,2151.95 4469.9,2150 4470.29,2148.05 4471.4,2146.4 4473.05,2145.29 4475,2144.9 4775,2144.9 4776.95,2145.29 4778.61,2146.4 4903.61,2271.4 4904.71,2273.05 4905.1,2275 4905.1,3550 4905.1,3604.9 5248.95,3604.9

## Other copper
Internal Plane 1 (plane layer: these items are gaps in the copper):
  lines w10: 2950,3625 2950,3325 2975,3300 3575,3300 3712.5,3162.5 3712.5,2962.5 3787.5,2887.5 3837.5,2887.5 4125,2600 4125,2200 4175,2150 4425,2150 ; 4475,2150 4775,2150 4900,2275 4900,3550 4900,3625 ; 5250,3625 5255,3620
  lines w12: 5255,10 5255,3620
  lines w40: 0,0 0,3625 7300,3625 7300,0 0,0

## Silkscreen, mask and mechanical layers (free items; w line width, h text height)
Top Overlay:
  text "-2.5V" at 5485,3435 h40
  text "EXTERNAL I/O" at 1315,3310 h40 r180
  text "CH-3" at 4710,3310 h40 r180
  text "REED SW." at 590,3305 h40 r180
  text "BATTERY" at 2730,3305 h40 r180
  text "CH-6" at 3720,3305 h40 r180
  text "CH-5" at 4015,3305 h40 r180
  text "CONSOLE" at 1935,3300 h40 r180
  text "Vint" at 6325,3280 h40
  text "HON-PRESS" at 3025,3260 h40
  text "AIN2" at 1285,3215 h40
  text "WAKE" at 50,3200 h60 r270
  text "AIN1" at 1055,3145 h40
  text "AIN0" at 1050,3060 h40
  text "Vtherm" at 6245,3015 h40
  text "CH-4" at 4595,2980 h40
  text "5V" at 3375,2820 h30
  text "Cap Adapter" at 6825,2805 h60 r90
  text "RESET" at 475,2700 h60 r270
  text "-2.5V" at 4615,2680 h40
  text "AUX-REF" at 6205,2645 h40
  text "JTAG" at 25,2575 h60 r270
  text "TEMP" at 4360,2565 h40
  text "BATTERY" at 2300,2505 h40
  text "+2.5V" at 4340,2460 h40
  text "+2.5V" at 6230,2375 h40 r90
  text "SeapHOx Rev-E" at 7225,2375 h50 r90
  text "3.3V" at 6040,2170 h40 r270
  text "3.3V" at 2160,2130 h40
  text "+3.75V" at 5635,1785 h40
  text "3.3V OPTO" at 2805,1760 h40
  text "DIC" at 25,1425 h60 r270
  text "-3.75V" at 6715,1400 h40
  text "IK+" at 6790,1315 h40
  text "IK-" at 6965,1310 h40
  text "UCSD/SIO" at 7225,875 h50 r90
  text "Martz Laboratory" at 7150,700 h50 r90
  text "ISO 5V" at 5895,620 h40
  text "Durafet" at 6950,575 h60 r90
  text "AUX1-RS232" at 4430,325 h40
  text "AUX1" at 2245,320 h40
  text "AUX2-RS232" at 3985,320 h40
  text "PUMP" at 2610,315 h40
  text "OPTODE" at 3015,315 h40
  text "MICROCAT" at 3515,315 h40
  text "AUX2" at 461.97,300 h40
  text "LEDS" at 1015,295 h40
  text "IB+" at 7120,155 h40
  text "ISO GND" at 5825,105 h40
  text "Cap Adapter" at 6225,100 h60 r90
  text "GND" at 4935,50 h40
Mechanical 1:
  the board outline again, w8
